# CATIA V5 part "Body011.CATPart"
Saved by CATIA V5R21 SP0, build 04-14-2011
Part number: Body011
Definition: design
Nomenclature: Body011
Source: Unknown
Bounding box of the stored display mesh (mm): x -0.35 to 0.35, y -1.5 to 1.5, z 0 to 0.1
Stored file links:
  C:\Users\beatr\OneDrive\Documents\UNB\2026_1\Pi1\Componentes eletronicos\Encoder\Body011.CATPart
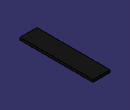
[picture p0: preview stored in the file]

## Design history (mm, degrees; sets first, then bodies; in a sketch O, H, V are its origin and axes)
Body1 "MANIFOLD_SOLID_BREP #5278" (main body)
  Solid1: solid without history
